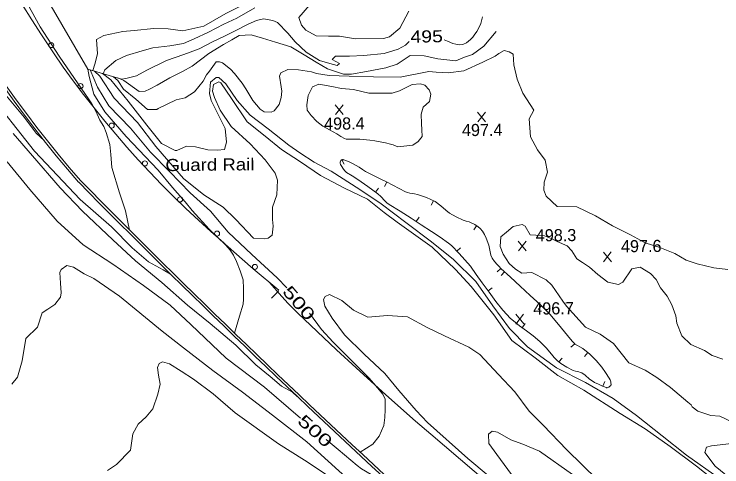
# Model space of a CAD drawing. Extents: x 2361284 to 2366480, y 6976556 to 6985346.
# Drawn here: x 2364656.7 to 2364937.1, y 6976880.3 to 6977059.8 of the extents above; entities that cross this region are included whole.
import ezdxf
from ezdxf.enums import TextEntityAlignment as Align

# ---------------------------------------------------------------- set-up
doc = ezdxf.new("R2010")
doc.units = 0
doc.header["$LTSCALE"] = 1.9
for name, color, linetype, lineweight in [('12', 7, 'Continuous', 13), ('13', 7, 'Continuous', 13), ('17', 7, 'Continuous', 13), ('27', 7, 'Continuous', 13), ('3', 7, 'Continuous', 13), ('5', 7, 'Continuous', 13), ('8', 7, 'Continuous', 13)]:
    doc.layers.add(name, color=color, linetype=linetype, lineweight=lineweight)

msp = doc.modelspace()

# ---------------------------------------------------------------- linework, layer by layer
at = {"layer": '12'}
for p, q in [((2364787.042, 6977019.971), (2364783.925, 6977023.822)), ((2364783.962, 6977019.942), (2364787.005, 6977023.851)), ((2364843.442, 6977017.077), (2364840.325, 6977020.928)), ((2364840.362, 6977017.048), (2364843.405, 6977020.957)), ((2364859.559, 6976965.948), (2364856.442, 6976969.799)), ((2364856.479, 6976965.919), (2364859.522, 6976969.828)), ((2364893.322, 6976961.638), (2364890.205, 6976965.489)), ((2364890.242, 6976961.609), (2364893.285, 6976965.518)), ((2364858.575, 6976936.956), (2364855.458, 6976940.807)), ((2364855.495, 6976936.927), (2364858.538, 6976940.836))]:
    msp.add_line(p, q, dxfattribs=at)
for points in [[(2364699.258, 6977034.045), (2364700.996, 6977034.242), (2364705.234, 6977035.362), (2364709.214, 6977037.53), (2364716.997, 6977041.434), (2364723.896, 6977043.81), (2364730.005, 6977046.057), (2364735.506, 6977048.97), (2364739.728, 6977050.86), (2364743.99, 6977052.961), (2364749.353, 6977055.792), (2364752.779, 6977057.295), (2364755.523, 6977057.881), (2364759.15, 6977057.256), (2364760.996, 6977056.443), (2364765.078, 6977052.201), (2364767.97, 6977048.818), (2364772.429, 6977044.731), (2364777.682, 6977041.341), (2364781.733, 6977040.16), (2364784.661, 6977039.358), (2364785.663, 6977040.237), (2364782.727, 6977041.809), (2364783.965, 6977043.141), (2364789.606, 6977043.065), (2364795.203, 6977043.438), (2364803.236, 6977044.174), (2364808.819, 6977045.937), (2364811.726, 6977047.504), (2364813.162, 6977048.898)], [(2364827.065, 6977049.62), (2364828.371, 6977049.003), (2364830.529, 6977048.135), (2364831.634, 6977047.812), (2364833.265, 6977047.619), (2364834.159, 6977047.73), (2364834.743, 6977047.9), (2364835.876, 6977048.439), (2364837.463, 6977049.656), (2364838.424, 6977050.667), (2364839.014, 6977051.401), (2364840.055, 6977052.944), (2364841.033, 6977054.846), (2364841.533, 6977056.123), (2364842.3, 6977058.747)], [(2364686.862, 6977037.658), (2364689.757, 6977030.814), (2364694.258, 6977023.386), (2364702.773, 6977014.528), (2364710.692, 6977005.112), (2364718.296, 6976997.364), (2364726.388, 6976988.889), (2364734.496, 6976981.697), (2364741.505, 6976973.353), (2364750.891, 6976964.501), (2364760.87, 6976955.217), (2364764.707, 6976951.293)], [(2364770.128, 6976899.661), (2364755.821, 6976911.946), (2364740.7, 6976923.443), (2364726.683, 6976936.8), (2364718.53, 6976944.403), (2364707.904, 6976952.263), (2364695.814, 6976960.627), (2364684.081, 6976968.267), (2364673.751, 6976977.729), (2364662.971, 6976990.277), (2364653.876, 6977001.211)], [(2364773.763, 6976941.288), (2364778.414, 6976934.832), (2364783.123, 6976929.697), (2364792.797, 6976919.918), (2364797.258, 6976915.61), (2364799.23, 6976913.338), (2364802.79, 6976909.092), (2364803.649, 6976907.12), (2364803.728, 6976903.052), (2364803.547, 6976899.919), (2364803.098, 6976896.744), (2364801.298, 6976892.477), (2364798.818, 6976889.283), (2364793.798, 6976886.146)], [(2364822.1, 6976858.693), (2364821.257, 6976858.485), (2364820.823, 6976858.491), (2364820.23, 6976858.686), (2364817.534, 6976860.5), (2364814.417, 6976862.768), (2364812.94, 6976863.997), (2364806.714, 6976869.848), (2364800.852, 6976875.282), (2364800, 6976875.997), (2364798.171, 6976877.264), (2364794.347, 6976879.591), (2364792.548, 6976880.903), (2364785.068, 6976887.193), (2364780.28, 6976891.157)]]:
    msp.add_lwpolyline(points, dxfattribs=at)
at = {"layer": '13'}
for points in [[(2364687.854, 6977037.367), (2364688.619, 6977039.995), (2364689.692, 6977043.974), (2364689.387, 6977049.741), (2364692.222, 6977051.268), (2364699.759, 6977052.84), (2364704.285, 6977053.273), (2364712.097, 6977054.017), (2364717.778, 6977054.001), (2364723.487, 6977053.166), (2364731.86, 6977054.985), (2364740.602, 6977059.99), (2364747.151, 6977063.392), (2364754.608, 6977068.973), (2364761.275, 6977073.426), (2364769.64, 6977079.327), (2364773.912, 6977083.407), (2364776.907, 6977086.006), (2364780.92, 6977090.583), (2364787.367, 6977100.906)], [(2364718.652, 6976956.765), (2364715.736, 6976958.438), (2364709.865, 6976961.641), (2364703.404, 6976967.11), (2364695.313, 6976975.484), (2364682.85, 6976986.276), (2364664.757, 6977005.405), (2364645.504, 6977029.833), (2364630.198, 6977053.479), (2364616.145, 6977072.746)], [(2364661.962, 6977063.832), (2364666.958, 6977054.798), (2364674.599, 6977043.151), (2364686.474, 6977025.842), (2364687.459, 6977024.222), (2364689.027, 6977021.347), (2364690.691, 6977017.782), (2364692.215, 6977015.188), (2364693.217, 6977012.897), (2364694.664, 6977008.04), (2364694.98, 6977004.182), (2364695.45, 6976998.937), (2364698.407, 6976988.903), (2364700.844, 6976981.797), (2364702.467, 6976974.172)], [(2364773.662, 6977063.354), (2364769.439, 6977058.444), (2364770.548, 6977055.353), (2364772.196, 6977053.459), (2364776.328, 6977051.138), (2364781.269, 6977051.085), (2364785.55, 6977051.056), (2364791.93, 6977050.046), (2364803, 6977050.061), (2364805.439, 6977050.836), (2364809.532, 6977054.164), (2364813.118, 6977060.919)], [(2364668.547, 6977009.631), (2364665.449, 6977012.543), (2364660.718, 6977018.927), (2364653.464, 6977027.689), (2364644.936, 6977038.079), (2364638.277, 6977046.285), (2364626.66, 6977061.656)], [(2364691.966, 6977036.166), (2364692.571, 6977037.742), (2364696.997, 6977041.334), (2364701.178, 6977043.434), (2364707.361, 6977045.202), (2364711.59, 6977046.352), (2364718.362, 6977047.267), (2364723.784, 6977048.158), (2364728.047, 6977049.969), (2364733.651, 6977052.672), (2364739.742, 6977055.73), (2364744.98, 6977058.151), (2364752.101, 6977062.299)], [(2364697.822, 6977034.462), (2364700.203, 6977033.433), (2364706.234, 6977029.111), (2364708.633, 6977029.203), (2364710.335, 6977030.06), (2364713.38, 6977031.589), (2364718.363, 6977034.527), (2364723.34, 6977037.055), (2364727.22, 6977039.141), (2364733.782, 6977044.154), (2364739.658, 6977047.799), (2364742.981, 6977049.641), (2364745.886, 6977051.239), (2364750.643, 6977051.604), (2364755.077, 6977050.186), (2364760.241, 6977048.675), (2364766.319, 6977046.783), (2364771.56, 6977043.613), (2364776.367, 6977040.729), (2364780.883, 6977038.062), (2364787.156, 6977036.039), (2364790.403, 6977036.042), (2364796.244, 6977036.978), (2364803.949, 6977038.551), (2364808.457, 6977039.924), (2364813.645, 6977043.343), (2364819.175, 6977043.306), (2364824.587, 6977042.037), (2364831.626, 6977041.234), (2364835.152, 6977042.738), (2364838.343, 6977043.748), (2364842.761, 6977047.099), (2364847.615, 6977052.926)], [(2364696.108, 6977034.966), (2364697.732, 6977033.48), (2364700.065, 6977030.092), (2364704.874, 6977026.067), (2364709.472, 6977021.911), (2364713.202, 6977021.976), (2364713.818, 6977022.402), (2364720.846, 6977025.849), (2364724.459, 6977026.624), (2364728.157, 6977028.959), (2364731.597, 6977033.202), (2364732.923, 6977035.756), (2364734.088, 6977037.157), (2364736.773, 6977040.882), (2364738.054, 6977040.825), (2364739.247, 6977040.516), (2364742.431, 6977037.976), (2364743.989, 6977036.181), (2364747.055, 6977032.459), (2364748.467, 6977030.172), (2364751.261, 6977025.478), (2364754.193, 6977022.126), (2364755.733, 6977021.101), (2364758.485, 6977020.887), (2364759.66, 6977021.418), (2364761.715, 6977023.948), (2364762.459, 6977026.705), (2364762.775, 6977029.248), (2364762.478, 6977031.015), (2364761.848, 6977035.191), (2364762.334, 6977036.458), (2364765.124, 6977037.832), (2364769.336, 6977037.672), (2364774.463, 6977036.951), (2364776.45, 6977036.209), (2364781.468, 6977035.427), (2364789.48, 6977035.233), (2364799.043, 6977034.984), (2364809.697, 6977034.745), (2364821.014, 6977037.053), (2364823.947, 6977036.771), (2364828.68, 6977036.546), (2364834.794, 6977037.234), (2364842.382, 6977040.687), (2364847.297, 6977043.173)], [(2364939.448, 6976958.505), (2364933.841, 6976959.211), (2364927.346, 6976960.81), (2364922.952, 6976962.257), (2364918.436, 6976964.924), (2364912.522, 6976967.338), (2364906.665, 6976969.123), (2364900.926, 6976972.299), (2364893.82, 6976975.912), (2364887.032, 6976979.837), (2364879.648, 6976983.417), (2364871.856, 6976983.543), (2364867.538, 6976987.612), (2364866.605, 6976989.934), (2364866.704, 6976993.205), (2364867.987, 6976997.147), (2364867.102, 6977001.869), (2364864.072, 6977006.05), (2364861.263, 6977011.204), (2364860.745, 6977018.329), (2364862.653, 6977021.687), (2364858.169, 6977028.465), (2364855.986, 6977034.046), (2364854.672, 6977039.673), (2364854.421, 6977043.951), (2364852.812, 6977044.866), (2364850.886, 6977045.407), (2364848.708, 6977044.127), (2364847.297, 6977043.173)], [(2364685.849, 6977037.968), (2364686.476, 6977035.064), (2364688.253, 6977028.02), (2364692.68, 6977021.031), (2364701.024, 6977011.28), (2364713.73, 6976997.98), (2364719.476, 6976991.045), (2364724.512, 6976985.352), (2364727.224, 6976981.938), (2364734.013, 6976974.592), (2364740.444, 6976968.293), (2364742.344, 6976966.16), (2364743.583, 6976964.222), (2364744.797, 6976961.763), (2364746.222, 6976958.057), (2364747.416, 6976954.519), (2364747.619, 6976951.01), (2364747.63, 6976946.76), (2364747.438, 6976944.847), (2364745.993, 6976940.094), (2364744.057, 6976933.295)], [(2364688.556, 6977037.164), (2364690.655, 6977035.174), (2364696.278, 6977026.466), (2364705.561, 6977016.754), (2364712.831, 6977007.292), (2364723.853, 6976994.676), (2364731.855, 6976988.182), (2364739.521, 6976983.285), (2364744.518, 6976978.432), (2364751.519, 6976970.988), (2364755.872, 6976970.72), (2364757.4, 6976970.944), (2364758.959, 6976972.139), (2364759.305, 6976975.693), (2364759.099, 6976978.411), (2364759.113, 6976983.281), (2364760.806, 6976988.198), (2364760.972, 6976993.919), (2364760.056, 6976996.681), (2364756.205, 6977002.004), (2364750.224, 6977008.378), (2364742.738, 6977015.228), (2364738.285, 6977021.745), (2364736.118, 6977026.725), (2364735.324, 6977029.227), (2364735.688, 6977031.921), (2364737.745, 6977032.994), (2364738.632, 6977032.579), (2364742.802, 6977026.398), (2364749.021, 6977017.137), (2364756.145, 6977011.394), (2364762.605, 6977006.145), (2364770.173, 6977001.177), (2364778.124, 6976995.863), (2364787.643, 6976990.843), (2364796.695, 6976986.379), (2364803.335, 6976981.182), (2364808.381, 6976977.379), (2364822.367, 6976967.371), (2364831.542, 6976958.599), (2364837.807, 6976951.808), (2364846.763, 6976940.552), (2364853.86, 6976930.47), (2364863.116, 6976923.567), (2364872.064, 6976916.491), (2364882.36, 6976910.689), (2364896.758, 6976901.476), (2364906.737, 6976895.35), (2364916.623, 6976888.423), (2364927.069, 6976880.602), (2364935.874, 6976873.626)], [(2364691.705, 6977036.244), (2364695.049, 6977033.724), (2364701.891, 6977025.269), (2364709.331, 6977015.75), (2364715.11, 6977008.504), (2364720.438, 6977005.734), (2364721.167, 6977005.781), (2364724.942, 6977007.387), (2364728.595, 6977007.112), (2364733.474, 6977006.048), (2364737.236, 6977005.844), (2364739.984, 6977006.08), (2364740.786, 6977009.008), (2364740.314, 6977014.505), (2364737.439, 6977020.317), (2364734.739, 6977025.511), (2364734.113, 6977028.256), (2364734.52, 6977032.82), (2364736.727, 6977034.612), (2364737.843, 6977034.592), (2364740.616, 6977032.188), (2364745.001, 6977025.509), (2364750.215, 6977019.788), (2364757.298, 6977014.336), (2364765.539, 6977007.873), (2364769.919, 6977004.825), (2364775.594, 6977001.159), (2364782.319, 6976997.472), (2364793.697, 6976990.32), (2364802.042, 6976984.629), (2364811.935, 6976977.143), (2364821.996, 6976969.528), (2364830.733, 6976962.55), (2364839.668, 6976953.806), (2364846.378, 6976944.208), (2364852.905, 6976935.12), (2364860.115, 6976927.889), (2364871.545, 6976919.516), (2364883.02, 6976913.795), (2364894.082, 6976907.36), (2364903.306, 6976900.637), (2364913.483, 6976892.634), (2364923.128, 6976884.905), (2364936.165, 6976875.689)], [(2364786.138, 6977011.219), (2364784.498, 6977012.315), (2364781.663, 6977013.858), (2364778.968, 6977015.432), (2364776.681, 6977017.25), (2364774.398, 6977019.588), (2364772.849, 6977021.664), (2364772.648, 6977023.782), (2364773.163, 6977027.547), (2364774.94, 6977030.974), (2364777.361, 6977031.977), (2364782.53, 6977031.056), (2364786.397, 6977030.263), (2364791.201, 6977029.888), (2364797.236, 6977028.386), (2364806.426, 6977028.413), (2364809.367, 6977029.421), (2364814.395, 6977031.839), (2364817.735, 6977032.193), (2364819.366, 6977031.606), (2364821.094, 6977029.783), (2364821.84, 6977028.05), (2364821.207, 6977025.193), (2364818.799, 6977022.84), (2364817.926, 6977020.082), (2364818.1, 6977016.425), (2364818.234, 6977013.926), (2364818.33, 6977011.205), (2364816.819, 6977009.281), (2364814.713, 6977007.861), (2364808.728, 6977007.144)], [(2364768.827, 6976908.259), (2364767.011, 6976909.902), (2364762.567, 6976912.26), (2364758.182, 6976916.078), (2364752.457, 6976920.714), (2364744.513, 6976928.5), (2364734.4, 6976937.123), (2364725.35, 6976944.477), (2364715.234, 6976953.383), (2364704.812, 6976962.043), (2364695.782, 6976970.298), (2364683.834, 6976981.695), (2364674.896, 6976990.891), (2364663.985, 6977003.548), (2364656.369, 6977012.517)], [(2364808.768, 6977007.144), (2364806.807, 6977007.935), (2364805.798, 6977008.256), (2364803.766, 6977008.786), (2364799.655, 6977009.588), (2364797.638, 6977009.863), (2364793.598, 6977010.26), (2364791.828, 6977010.275), (2364789.46, 6977010.172), (2364788.279, 6977010.24), (2364787.525, 6977010.432), (2364786.138, 6977011.219)], [(2364855.372, 6976958.665), (2364852.849, 6976960.971), (2364850.404, 6976964.637), (2364849.295, 6976967.688), (2364849.469, 6976971.48), (2364851.712, 6976973.311), (2364854.401, 6976975.637), (2364857.904, 6976976.34), (2364859.13, 6976975.792), (2364861.153, 6976972.301), (2364865.676, 6976972.034), (2364866.858, 6976971.835), (2364869.517, 6976970.86), (2364871.829, 6976969.632), (2364875.775, 6976967.89), (2364877.674, 6976965.927), (2364879.624, 6976962.815), (2364881.828, 6976961.347), (2364884.595, 6976959.533), (2364887.964, 6976956.575), (2364891.933, 6976953.483), (2364896.192, 6976952.553), (2364897.914, 6976953.48), (2364901.373, 6976958.873), (2364904.707, 6976959.464), (2364908.81, 6976957.003), (2364911.024, 6976954.584), (2364912.795, 6976951.261), (2364915.477, 6976947.986), (2364917.289, 6976944.592), (2364918.86, 6976940.227), (2364919.238, 6976937.311), (2364921.177, 6976932.32), (2364924.83, 6976928.844), (2364930.242, 6976926.466), (2364933.262, 6976924.404), (2364937.515, 6976923.054)], [(2364789.545, 6976874.925), (2364772.718, 6976890.235), (2364759.037, 6976900.776), (2364747.21, 6976909.904), (2364735.436, 6976918.552), (2364723.791, 6976927.513), (2364715.327, 6976934.142), (2364698.416, 6976947.993), (2364688.247, 6976955.046), (2364684.41, 6976956.79), (2364680.275, 6976959.421), (2364677.62, 6976960.084), (2364675.323, 6976958.587), (2364674.864, 6976957.379), (2364675.044, 6976953.171), (2364675.301, 6976949.283), (2364675.012, 6976947.572), (2364672.875, 6976944.729), (2364670.003, 6976942.821), (2364667.796, 6976941.44), (2364665.97, 6976935.682), (2364661.293, 6976931.149), (2364659.916, 6976922.394), (2364657.999, 6976915.851), (2364655.845, 6976913.095)], [(2364924.928, 6976904.854), (2364923.637, 6976905.972), (2364916.791, 6976911.776), (2364911.293, 6976915.754), (2364906.666, 6976918.59), (2364900.238, 6976921.589), (2364894.204, 6976929.223), (2364888.879, 6976932.883), (2364883.001, 6976935.746), (2364875.543, 6976943.985), (2364874.023, 6976945.952), (2364869.743, 6976952.312), (2364867.448, 6976954.518), (2364861.755, 6976957.346), (2364857.867, 6976957.099), (2364855.372, 6976958.665)], [(2364887.878, 6976875.15), (2364875.643, 6976887.134), (2364866.321, 6976896.806), (2364860.727, 6976902.424), (2364855.084, 6976910.059), (2364848.608, 6976916.908), (2364841.205, 6976924.83), (2364836.835, 6976927.818), (2364827.261, 6976932.277), (2364820.33, 6976935.51), (2364812.5, 6976939.816), (2364804.594, 6976940.291), (2364796.869, 6976939.717), (2364791.202, 6976942.483), (2364786.466, 6976946.23), (2364781.603, 6976948.643), (2364779.98, 6976947.898), (2364779.288, 6976946.62), (2364779.807, 6976944.035), (2364782.753, 6976939.223), (2364787.617, 6976932.6), (2364795.389, 6976924.993)], [(2364795.389, 6976924.993), (2364803.511, 6976917.379), (2364809.148, 6976910.553), (2364815.983, 6976902.618), (2364820.517, 6976897.97), (2364836.494, 6976883.691), (2364844.539, 6976876.888), (2364851.563, 6976870.074), (2364853.72, 6976867.344), (2364858.6, 6976863.221), (2364861.612, 6976857.789), (2364862.698, 6976853.938), (2364865.257, 6976848.783), (2364865.532, 6976845.166), (2364864.446, 6976839.515), (2364862.437, 6976835.176), (2364860.93, 6976832.76), (2364856.728, 6976829.783), (2364854.599, 6976829.59)], [(2364782.717, 6976875.72), (2364771.717, 6976882.956), (2364761.456, 6976889.388), (2364744.308, 6976901.697), (2364735.524, 6976909.333), (2364727.78, 6976915.099), (2364722.839, 6976918.282), (2364718.251, 6976921.159), (2364715.524, 6976921.906), (2364714.209, 6976921.32), (2364713.494, 6976919.714), (2364713.913, 6976916.697), (2364714.507, 6976913.113), (2364713.674, 6976909.205), (2364711.62, 6976903.276), (2364708.97, 6976900.11), (2364705.798, 6976897.259), (2364703.685, 6976893.379), (2364702.736, 6976887), (2364697.269, 6976881.308), (2364693.742, 6976878.863)], [(2364965.24, 6976877.515), (2364959.913, 6976884.425), (2364956.92, 6976887.937), (2364955.478, 6976889.213), (2364946.789, 6976895.351), (2364936.259, 6976900.461), (2364932.667, 6976900.737), (2364927.549, 6976902.368), (2364925.326, 6976904.068), (2364924.928, 6976904.854)], [(2364877.866, 6976877.344), (2364864.829, 6976886.491), (2364858.251, 6976889.349), (2364853.475, 6976891.073), (2364848.186, 6976894.013), (2364846.022, 6976894.513), (2364844.614, 6976893.239), (2364844.749, 6976889.56), (2364847.929, 6976885.24), (2364853.755, 6976877.335)], [(2364960.399, 6976871.209), (2364956.855, 6976881.116), (2364952.714, 6976887.223), (2364949.638, 6976889.157), (2364940.963, 6976889.545), (2364933.002, 6976888.599), (2364930.957, 6976888.09), (2364930.275, 6976885.976), (2364934.379, 6976880.542), (2364945.747, 6976871.4)]]:
    msp.add_lwpolyline(points, dxfattribs=at)
at = {"layer": '17'}
msp.add_lwpolyline([(2364659.944, 6977063.583), (2364663.702, 6977057.498), (2364667.549, 6977051.534), (2364671.465, 6977045.601), (2364672.327, 6977044.379), (2364676.181, 6977038.806), (2364680.142, 6977033.353), (2364684.204, 6977027.971), (2364688.345, 6977022.6), (2364692.595, 6977017.34), (2364696.924, 6977012.182), (2364701.334, 6977007.043), (2364705.841, 6977002.016), (2364710.438, 6976997.079), (2364715.145, 6976992.184), (2364719.901, 6976987.419), (2364724.727, 6976982.704), (2364729.681, 6976978.061), (2364734.683, 6976973.558), (2364739.776, 6976969.117), (2364740.482, 6976968.503), (2364751.435, 6976958.837), (2364761.536, 6976950.333)], dxfattribs=at)
for centre in [(2364671.421, 6977047.489), (2364682.984, 6977031.25), (2364695.356, 6977015.606), (2364708.512, 6977000.615), (2364722.443, 6976986.333), (2364737.081, 6976972.795), (2364752.085, 6976959.596)]:
    msp.add_circle(centre, 1, dxfattribs=at)
at = {"layer": '27'}
for p, q in [((2364786.535, 6977002.073), (2364787.483, 6977000.312)), ((2364804.341, 6976993.202), (2364803.468, 6976991.393)), ((2364799.878, 6976989.228), (2364801.053, 6976990.85)), ((2364822.782, 6976985.807), (2364821.929, 6976983.998)), ((2364816.021, 6976977.582), (2364817.115, 6976979.252)), ((2364839.928, 6976975.889), (2364838.813, 6976974.239)), ((2364832.093, 6976965.793), (2364833.55, 6976967.177)), ((2364849.529, 6976958.92), (2364848.041, 6976957.576)), ((2364850.951, 6976957.653), (2364849.615, 6976956.16)), ((2364844.463, 6976950.121), (2364846.071, 6976951.297)), ((2364865.671, 6976944.122), (2364864.244, 6976942.718)), ((2364857.943, 6976935.488), (2364859.127, 6976937.099)), ((2364878.785, 6976929.037), (2364877.257, 6976927.742)), ((2364883.937, 6976925.655), (2364882.692, 6976924.093)), ((2364872.522, 6976921.916), (2364873.778, 6976923.469)), ((2364889.874, 6976912.35), (2364890.697, 6976914.168))]:
    msp.add_line(p, q, dxfattribs=at)
for points in [[(2364849.529, 6976958.92), (2364848.791, 6976959.743), (2364848.053, 6976960.576), (2364847.011, 6976961.765), (2364846.039, 6976963.026), (2364845.489, 6976964.221), (2364844.701, 6976968.164), (2364843.655, 6976970.994), (2364843.011, 6976972.368), (2364842.209, 6976973.701), (2364841.288, 6976974.802), (2364840.511, 6976975.505), (2364839.203, 6976976.382), (2364837.786, 6976977.099), (2364836.983, 6976977.381), (2364835.741, 6976977.68), (2364834.537, 6976978.078), (2364831.834, 6976979.422), (2364829.218, 6976980.948), (2364827.748, 6976982.034), (2364825.68, 6976983.854), (2364823.465, 6976985.483), (2364820.069, 6976987.081), (2364816.519, 6976988.297), (2364815.316, 6976988.576), (2364813.463, 6976988.848), (2364812.561, 6976989.049), (2364811.698, 6976989.36), (2364809.226, 6976990.678), (2364806.762, 6976992.025), (2364804.23, 6976993.251), (2364801.698, 6976994.477), (2364798.815, 6976995.909), (2364795.96, 6976997.402), (2364794.672, 6976998.23), (2364793.404, 6976999.088), (2364792.237, 6976999.787), (2364791.051, 6977000.456), (2364789.204, 6977001.308), (2364787.317, 6977002.01), (2364787.076, 6977002.078), (2364786.896, 6977002.116), (2364786.745, 6977002.115), (2364786.535, 6977002.073), (2364786.346, 6977001.971), (2364786.138, 6977001.759), (2364786.01, 6977001.538), (2364785.915, 6977001.097), (2364785.918, 6977000.747), (2364786.033, 6977000.228), (2364786.227, 6976999.78), (2364787.152, 6976998.308), (2364787.709, 6976997.624), (2364788.374, 6976997.05), (2364790.627, 6976995.621), (2364792.861, 6976994.203), (2364796.867, 6976991.421), (2364800.815, 6976988.548), (2364801.975, 6976987.519), (2364803.571, 6976985.824), (2364804.398, 6976985.022), (2364805.315, 6976984.311), (2364809.622, 6976981.621), (2364813.928, 6976978.942), (2364818.012, 6976976.271), (2364822.098, 6976973.6), (2364825.489, 6976971.362), (2364828.822, 6976969.003), (2364829.931, 6976968.074), (2364832.942, 6976964.911), (2364835.266, 6976962.433), (2364837.44, 6976959.845), (2364839.801, 6976956.567), (2364842.143, 6976953.279), (2364844.848, 6976949.595), (2364847.572, 6976945.921), (2364850.335, 6976942.446), (2364853.387, 6976939.195), (2364855.142, 6976937.651), (2364856.966, 6976936.208), (2364859.655, 6976934.224), (2364862.334, 6976932.23), (2364864.986, 6976929.955), (2364867.529, 6976927.549), (2364869.653, 6976925.02), (2364870.685, 6976923.699), (2364871.827, 6976922.479), (2364873.298, 6976921.293), (2364875.693, 6976919.816), (2364878.234, 6976918.58), (2364879.077, 6976918.288), (2364880.38, 6976917.97), (2364881.022, 6976917.786), (2364881.625, 6976917.532), (2364882.913, 6976916.674), (2364884.707, 6976915.131), (2364885.634, 6976914.41), (2364886.64, 6976913.83), (2364888.227, 6976913.095), (2364889.824, 6976912.37), (2364890.537, 6976912.047)], [(2364878.785, 6976929.037), (2364877.956, 6976930.009), (2364877.136, 6976930.991), (2364874.738, 6976933.897), (2364872.341, 6976936.815), (2364868.862, 6976940.862), (2364865.126, 6976944.676), (2364861.161, 6976948.29), (2364857.187, 6976951.902), (2364853.403, 6976955.466), (2364849.529, 6976958.92)], [(2364890.537, 6976912.047), (2364891.25, 6976911.723), (2364891.431, 6976911.665), (2364891.601, 6976911.657), (2364891.88, 6976911.719), (2364892.318, 6976911.953), (2364892.745, 6976912.288), (2364892.923, 6976912.449), (2364893.032, 6976912.58), (2364893.14, 6976912.781), (2364893.179, 6976912.882), (2364893.188, 6976912.992), (2364893.142, 6976913.601), (2364893.038, 6976914.07), (2364892.781, 6976914.768), (2364892.435, 6976915.425), (2364891.023, 6976917.711), (2364889.463, 6976919.877), (2364887.227, 6976922.516), (2364884.784, 6976924.983), (2364881.952, 6976927.237), (2364878.755, 6976929.056)]]:
    msp.add_lwpolyline(points, dxfattribs=at)
at = {"layer": '3'}
for p, q in [((2364682.295, 6976993.124), (2364682.257, 6976993.165)), ((2364682.978, 6976993.798), (2364682.979, 6976993.798))]:
    msp.add_line(p, q, dxfattribs=at)
msp.add_lwpolyline([(2364757.917, 6976953.378), (2364762.76, 6976947.834), (2364765.247, 6976945.129), (2364769.123, 6976941.203), (2364784.451, 6976926.688), (2364792.192, 6976919.528), (2364803.91, 6976908.912), (2364815.767, 6976898.452), (2364821.751, 6976893.282), (2364874.16, 6976848.558), (2364935.226, 6976795.645), (2364953.87, 6976779.839), (2364978.85, 6976758.907), (2364991.259, 6976748.346), (2365006.927, 6976734.64), (2365027.687, 6976716.215), (2365038.135, 6976707.08), (2365065.071, 6976683.995), (2365078.625, 6976672.552)], dxfattribs=at)
for centre, radius, start, end in [((2365003.154, 6977274.355), 426.665, 191.92895, 221.22682), ((2365003.154, 6977274.355), 425.705, 191.92895, 221.22682), ((2367201.322, 6979475.289), 3536.473, 224.5777, 227.57296), ((2367201.322, 6979475.289), 3535.513, 224.5777, 227.57296)]:
    msp.add_arc(centre, radius, start, end, dxfattribs=at)
at = {"layer": '5'}
msp.add_lwpolyline([(2364761.447, 6976950.043), (2364760.061, 6976948.615), (2364758.667, 6976947.18)], dxfattribs=at)
at = {"layer": '8'}
msp.add_lwpolyline([(2364699.258, 6977034.045), (2364685.859, 6977037.948), (2364670.405, 6977064.542), (2364679.885, 6977069.893)], dxfattribs=at)

# ---------------------------------------------------------------- texts
at = {"layer": '12'}
for s, rotation, width, p in [(' 495 ', 0.705, 1.2, (2364820.152, 6977048.551)), (' 500 ', 310.626, 1.45, (2364767.72, 6976943.704)), (' 500 ', 317.959, 1.45, (2364774.334, 6976892.767))]:
    msp.add_text(s, height=4.8, rotation=rotation, dxfattribs=dict(at, width=width)).set_placement(p, align=Align.CENTER)
for s, p in [('498.4', (2364779.512, 6977013.948)), ('497.4', (2364834.13, 6977011.396)), ('498.3', (2364863.368, 6976969.672)), ('497.6', (2364897.13, 6976965.362)), ('496.7', (2364862.384, 6976940.68))]:
    msp.add_text(s, height=4.799, rotation=0.545, dxfattribs=at).set_placement(p)
at = {"layer": '17', "width": 1.15}
msp.add_text('Guard Rail', height=4.799, rotation=0.545, dxfattribs=at).set_placement((2364716.654, 6976997.548))

doc.saveas('drawing.dxf')
